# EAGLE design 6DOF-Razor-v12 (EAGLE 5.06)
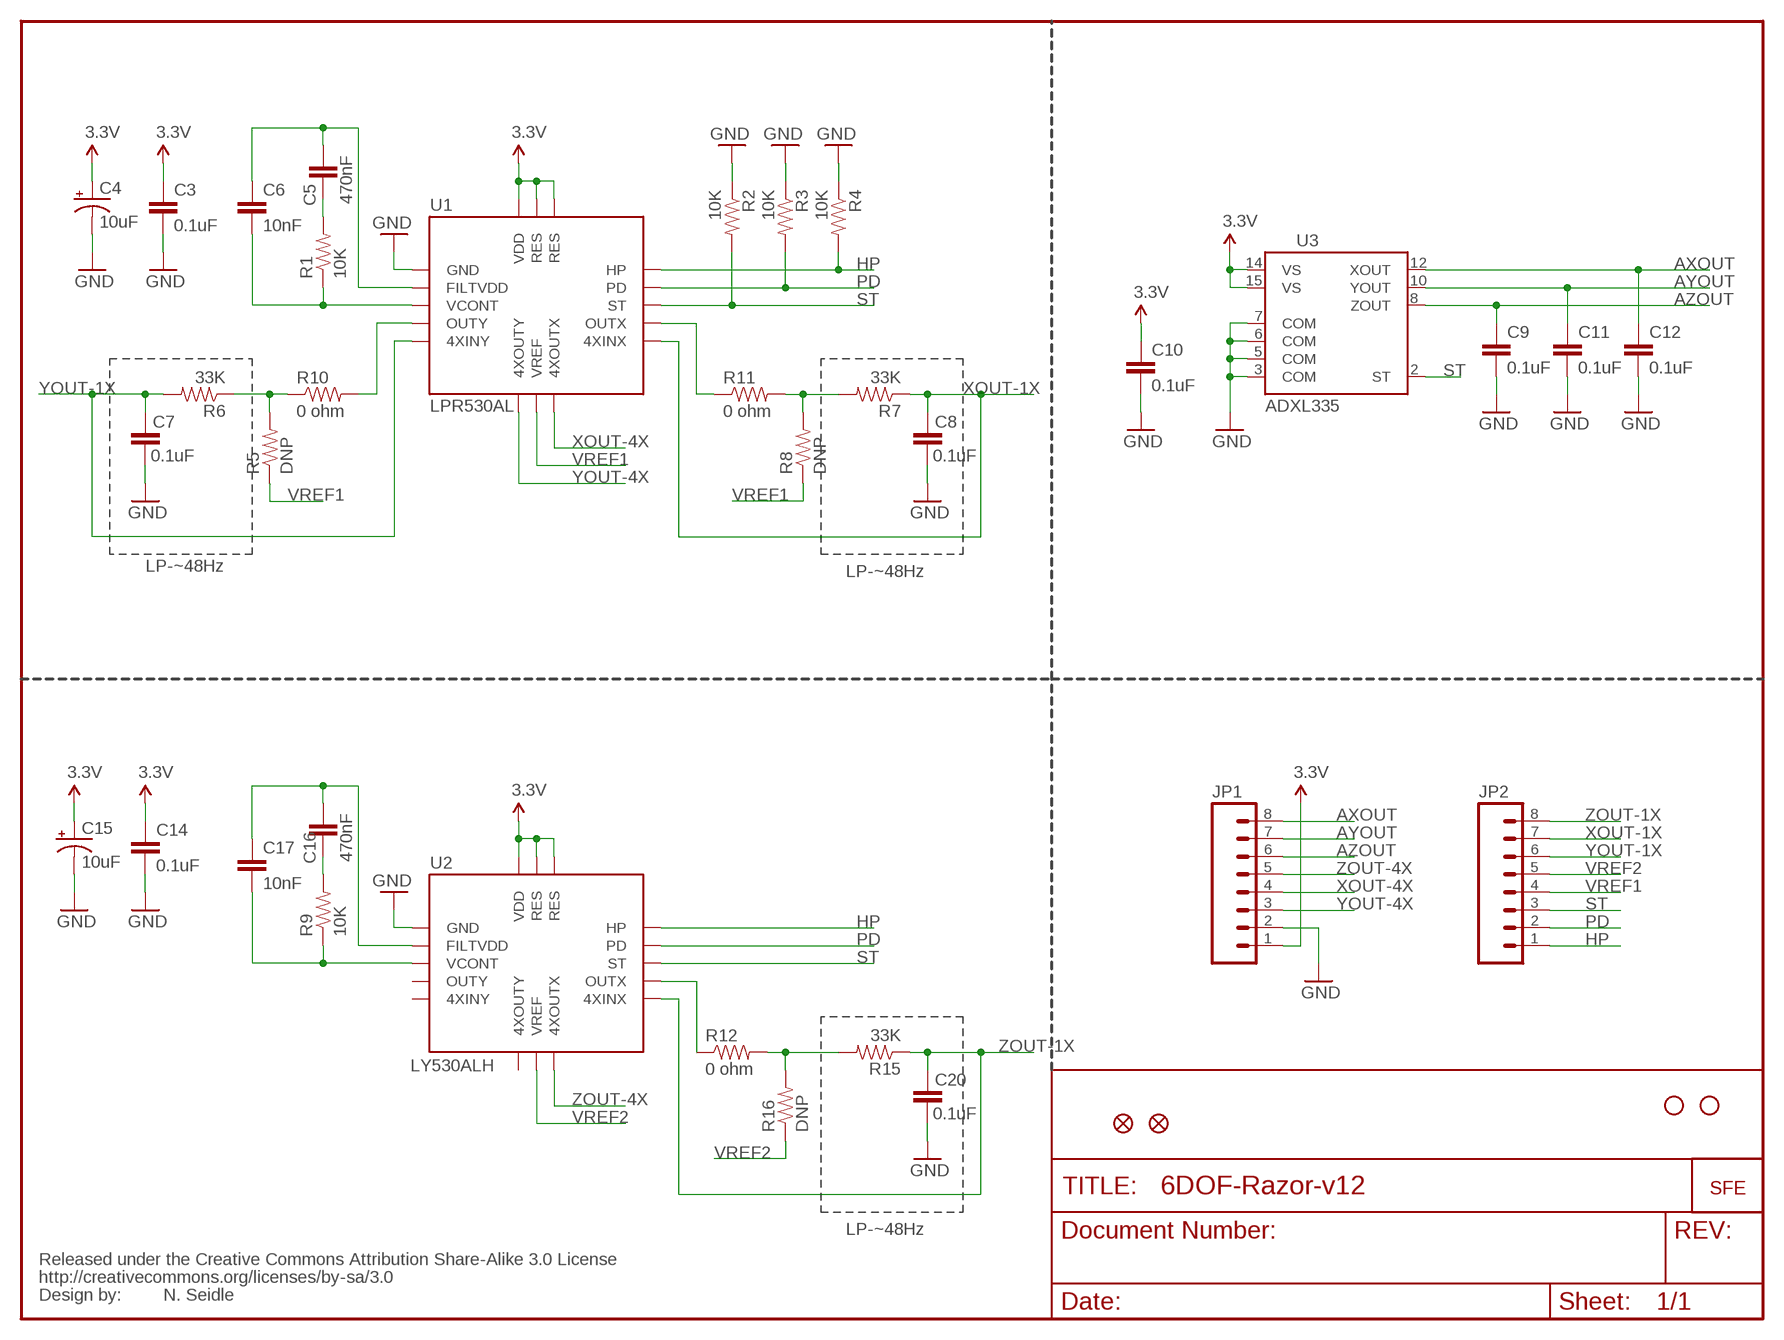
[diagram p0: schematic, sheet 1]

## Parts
C3  0.1uF  CAP0402-CAP  [0402-CAP]
C4  10uF  CAP_POL1206  [EIA3216]
C5  470nF  CAP0402-CAP  [0402-CAP]
C6  10nF  CAP0402-CAP  [0402-CAP]
C7  0.1uF  CAP0402-CAP  [0402-CAP]
C8  0.1uF  CAP0402-CAP  [0402-CAP]
C9  0.1uF  CAP0402-CAP  [0402-CAP]
C10  0.1uF  CAP0402-CAP  [0402-CAP]
C11  0.1uF  CAP0402-CAP  [0402-CAP]
C12  0.1uF  CAP0402-CAP  [0402-CAP]
C14  0.1uF  CAP0402-CAP  [0402-CAP]
C15  10uF  CAP_POL1206  [EIA3216]
C16  470nF  CAP0402-CAP  [0402-CAP]
C17  10nF  CAP0402-CAP  [0402-CAP]
C20  0.1uF  CAP0402-CAP  [0402-CAP]
JP1  M08  [1X08]
JP2  M08  [1X08]
JP3  LOGO-SFENEW  [SFE-NEW-WEBLOGO]
JP4  FIDUCIAL1X2  [FIDUCIAL-1X2]
JP5  FIDUCIAL1X2  [FIDUCIAL-1X2]
R1  10K  RESISTOR0402-RES  [0402-RES]
R2  10K  RESISTOR0402-RES  [0402-RES]
R3  10K  RESISTOR0402-RES  [0402-RES]
R4  10K  RESISTOR0402-RES  [0402-RES]
R5  DNP  RESISTOR0402-RES  [0402-RES]
R6  33K  RESISTOR0402-RES  [0402-RES]
R7  33K  RESISTOR0402-RES  [0402-RES]
R8  DNP  RESISTOR0402-RES  [0402-RES]
R9  10K  RESISTOR0402-RES  [0402-RES]
R10  0 ohm  RESISTOR0402-RES  [0402-RES]
R11  0 ohm  RESISTOR0402-RES  [0402-RES]
R12  0 ohm  RESISTOR0402-RES  [0402-RES]
R15  33K  RESISTOR0402-RES  [0402-RES]
R16  DNP  RESISTOR0402-RES  [0402-RES]
U1  LPR530AL  ST-GYROLGA  [ST-GYRO]
U2  LY530ALH  ST-GYROLGA  [ST-GYRO]
U3  ADXL335  ADXL330SMD  [LFCSP-16]
U$1  CREATIVE_COMMONS  [CREATIVE_COMMONS]
U$2  STAND-OFF  [STAND-OFF]
U$4  STAND-OFF  [STAND-OFF]

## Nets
3.3V: C3.1 C4.A(+) C10.1 C14.1 C15.A(+) JP1.1 U1.14(RES) U1.15(RES) U1.16(VDD) U2.14(RES) U2.15(RES) U2.16(VDD) U3.14(VS) U3.15(VS)
AXOUT: C12.1 JP1.8 U3.12(XOUT)
AYOUT: C11.1 JP1.7 U3.10(YOUT)
AZOUT: C9.1 JP1.6 U3.8(ZOUT)
F1: C5.1 C6.1 U1.2(FILTVDD)
F2: C6.2 R1.1 U1.3(VCONT)
F3: C16.1 C17.1 U2.2(FILTVDD)
F4: C17.2 R9.1 U2.3(VCONT)
GND: C3.2 C4.C(-) C7.1 C8.1 C9.2 C10.2 C11.2 C12.2 C14.2 C15.C(-) C20.1 JP1.2 R2.1 R3.1 R4.1 U1.1(GND) U2.1(GND) U3.3(COM) U3.5(COM) U3.6(COM) U3.7(COM)
HP: JP2.1 R4.2 U1.13(HP) U2.13(HP)
N$1: R10.2 U1.4(OUTY)
N$2: C5.2 R1.2
N$3: R11.1 U1.10(OUTX)
N$4: R5.2 R6.1 R10.1
N$6: R7.2 R8.2 R11.2
N$8: C16.2 R9.2
N$9: R12.1 U2.10(OUTX)
N$10: R12.2 R15.2 R16.2
PD: JP2.2 R3.2 U1.12(PD) U2.12(PD)
ST: JP2.3 R2.2 U1.11(ST) U2.11(ST) U3.2(ST)
VREF1: JP2.4 R5.1 R8.1 U1.7(VREF)
VREF2: JP2.5 R16.1 U2.7(VREF)
XOUT-1X: C8.2 JP2.7 R7.1 U1.9(4XINX)
XOUT-4X: JP1.4 U1.8(4XOUTX)
YOUT-1X: C7.2 JP2.6 R6.2 U1.5(4XINY)
YOUT-4X: JP1.3 U1.6(4XOUTY)
ZOUT-1X: C20.2 JP2.8 R15.1 U2.9(4XINX)
ZOUT-4X: JP1.5 U2.8(4XOUTX)
Unconnected: U2.4(OUTY) U2.5(4XINY) U2.6(4XOUTY)

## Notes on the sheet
- LP-~48Hz
- LP-~48Hz
- LP-~48Hz
- N. Seidle

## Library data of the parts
C3 C5-C12 C14 C16 C17 C20 = SparkFun:CAP: Capacitor
C4 C15 = SparkFun:CAP_POL: Capacitor Polarized
JP1 JP2 = SparkFun:M08: Header 8 Standard 8-pin 0.1" header. Use with straight break away headers (SKU : PRT-00116), right angle break away headers (PRT-00553), swiss pins (PRT-00743), machine pins (PRT-00117), and female headers (PRT-00115).
JP3 = SparkFun:LOGO-SFE: Spark Fun Electronics PCB Logo
JP4 JP5 = SparkFun:FIDUCIAL: Fiducial Alignment Points
R1-R12 R15 R16 = SparkFun:RESISTOR: Resistor
U1 U2 = SparkFun:ST-GYRO
U3 = SparkFun:ADXL330: Triple Axis Accelerometer Analog Devices ADXL330 +/-3g 2.4V-5.25V Analog output. Spark Fun Electronics SKU : COM-00730. Center pad paste layer has been reduced to avoid shorting.
U$1 = SparkFun:CREATIVE_COMMONS
U$2 U$4 = SparkFun:STAND-OFF: Stand Off

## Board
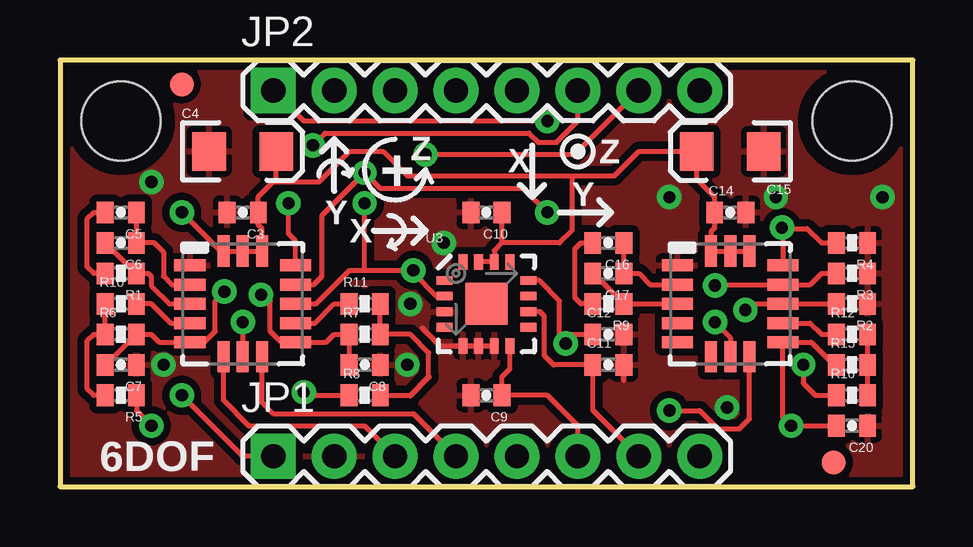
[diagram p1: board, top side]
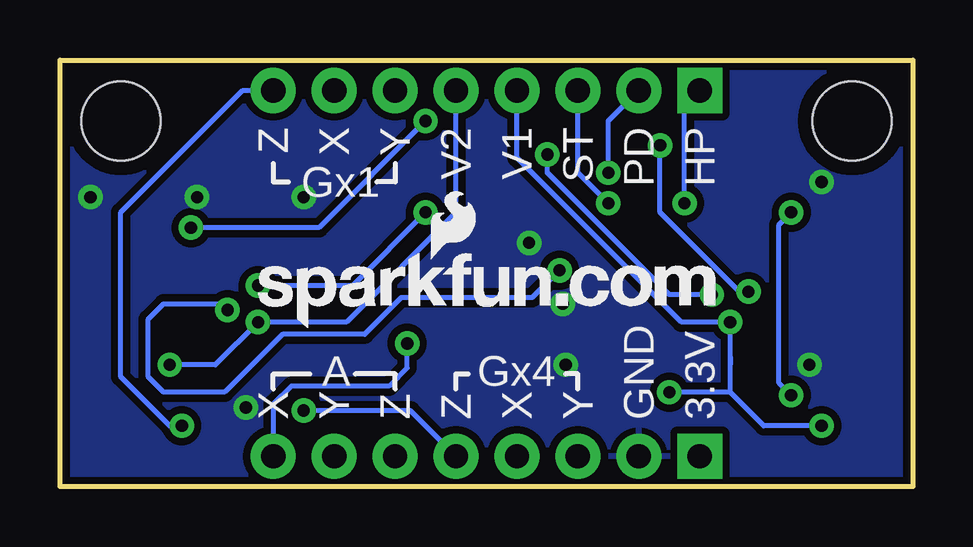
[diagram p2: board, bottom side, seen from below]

Size 35.56 x 17.78 mm. Coordinates in mm from the lower left corner, seen from the top.
Outline: 0,0 35.56,0 35.56,17.78 0,17.78 0,0
Copper layers (1*16): Top 0.035mm / dielectric 1.5mm / Bottom 0.035mm
Design rules "SparkFun": minimum track width 8mil, minimum drill 20mil, track to track 8mil, track to pad 8mil, pad to pad 8mil, via to via 8mil, smd to smd 8mil, copper to edge 9mil, drill to drill 8mil, minimum pad ring 12mil, minimum via ring 10mil, stop-mask expansion 4mil, vias tented up to drill 20mil, thermal gap 10mil

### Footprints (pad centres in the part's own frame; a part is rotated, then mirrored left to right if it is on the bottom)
0402-CAP = smd 0.7 x 0.9: 1 -0.65,0; 2 0.65,0
EIA3216 = smd 1.4 x 1.6: A 1.4,0; C -1.4,0
1X08 = drill 1.016 pad 1.88 square: 1 0,0 | drill 1.016 pad 1.88 round: 2 2.54,0; 3 5.08,0; 4 7.62,0; 5 10.16,0; 6 12.7,0; 7 15.24,0; 8 17.78,0
FIDUCIAL-1X2 = smd 1 x 1: 1 0,0
0402-RES = smd 0.7 x 0.9: 1 -0.65,0; 2 0.65,0
ST-GYRO@1 = smd 1.3 x 0.5: 1 -2.2,1.6; 2 -2.2,0.8; 3 -2.2,0; 4 -2.2,-0.8; 5 -2.2,-1.6; 9 2.2,-1.6; 10 2.2,-0.8; 11 2.2,0; 12 2.2,0.8; 13 2.2,1.6 | smd 0.5 x 1.3: 6 -0.8,-2.2; 7 0,-2.2; 8 0.8,-2.2; 14 0.8,2.2; 15 0,2.2; 16 -0.8,2.2
LFCSP-16 = smd 1.75 x 1.75: 0 0,0 | smd 0.65 x 0.37: 1 -1.75,0.975; 2 -1.75,0.325; 3 -1.75,-0.325; 4 -1.75,-0.975; 9 1.75,-0.975; 10 1.75,-0.325; 11 1.75,0.325; 12 1.75,0.975 | smd 0.37 x 0.65: 5 -0.975,-1.75; 6 -0.325,-1.75; 7 0.325,-1.75; 8 0.975,-1.75; 13 0.975,1.75; 14 0.325,1.75; 15 -0.325,1.75; 16 -0.975,1.75
STAND-OFF = hole 3.302: 0,0

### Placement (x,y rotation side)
C3  7.62,11.43 180 top
C4  7.62,13.97 0 top
C5  2.54,11.43 180 top
C6  2.54,10.16 180 top
C7  2.54,5.08 180 top
C8  12.7,5.08 180 top
C9  17.78,3.81 180 top
C10  17.78,11.43 180 top
C11  22.86,5.08 0 top
C12  22.86,6.35 0 top
C14  27.94,11.43 0 top
C15  27.94,13.97 180 top
C16  22.86,10.16 180 top
C17  22.86,8.89 180 top
C20  33.02,2.54 180 top
JP1  8.89,1.27 0 top
JP2  8.89,16.51 0 top
JP3  27.3,6.6 0 bottom
JP4  32.26,1.02 0 top
JP5  5.08,16.76 0 top
R1  2.54,8.89 180 top
R2  33.02,7.62 180 top
R3  33.02,8.89 180 top
R4  33.02,10.16 180 top
R5  2.54,3.81 180 top
R6  2.54,6.35 0 top
R7  12.7,6.35 0 top
R8  12.7,3.81 0 top
R9  22.86,7.62 180 top
R10  2.54,7.62 0 top
R11  12.7,7.62 0 top
R12  33.02,6.35 0 top
R15  33.02,5.08 0 top
R16  33.02,3.81 0 top
U1  LPR530AL  [ST-GYRO@1]  7.62,7.62 0 top
U2  LY530ALH  [ST-GYRO@1]  27.94,7.62 0 top
U3  17.78,7.62 0 top
U$1  not placed on the board
U$2  2.54,15.24 0 top
U$4  33.02,15.24 0 top

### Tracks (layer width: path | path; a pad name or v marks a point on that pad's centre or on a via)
3.3V  (via drill 0.51)
  Top 0.203: U1.14 8.42,10.76 8.27,10.91 C3.1 8.27,12.08 8.89,12.7 9.02,12.7 | U1.14 U1.15 U1.16 6.69,9.82 v5.08,11.43 | U3.15 U3.14 18.11,9.85 18.41,10.16 | U2.14 U2.15 U2.16 | U1.14 8.55,9.82 | JP1.1 7.62,1.27 v5.08,3.81 | U2.16 27.01,9.82 | U2.16 27.14,10.63 27.29,10.78 C14.1 27.29,12.08 26.54,12.83 C15.A 24.13,13.97 23.11,12.95 21.34,12.95 | C10.1 18.43,10.18 18.41,10.16 | C4.A 9.02,12.7 | 18.41,10.16 20.83,10.16 21.34,10.67 21.34,12.95 | 21.34,12.95 14.48,12.95 13.46,13.97 12.06,13.97 10.79,12.7 9.02,12.7
  Bottom 0.203: v5.08,3.81 5.59,4.32 5.59,10.92 v5.08,11.43
AXOUT  (via drill 0.51)
  Top 0.203: U3.12 19.98,8.6 20.83,7.75 20.83,6.22 v21.08,5.97 21.08,6.35 C12.1
  Bottom 0.203: JP1.8 26.67,3.43 25.91,4.19 21.84,4.19 21.08,4.95 v21.08,5.97
AYOUT
  Top 0.203: JP1.7 22.21,3.19 C11.1 20.57,5.08 20.19,5.46 20.19,7.11 20.01,7.29 U3.10
AZOUT
  Top 0.203: JP1.6 21.59,2.54 20.32,3.81 C9.1 18.43,4.59 18.75,4.91 U3.8
F1
  Top 0.203: C5.1 C6.1 3.94,10.16 4.32,9.78 4.32,8.76 4.66,8.42 U1.2
F2
  Top 0.203: C6.2 3.16,8.89 R1.1 3.68,8.89 3.81,8.76 3.81,8.38 4.57,7.62 U1.3
F3
  Top 0.203: C16.1 C17.1 24.13,8.89 24.6,8.42 U2.2
F4
  Top 0.203: U2.3 R9.1 22.24,8.89 C17.2
GND  (via drill 0.51)
  Top 0.203: U3.7 U3.6 U3.5 15.85,5.87 15.11,6.6 | 23.51,4.43 C11.2
  other vias: 3.81,12.7 27.81,3.3 25.4,12.06 34.29,12.06 4.32,5.08 29.84,12.06 16,10.16 14.48,5.08 14.61,7.62
  pour Bottom (isolate 0.305): 0,17.78 35.56,17.78 35.56,0 0,0
  pour Top (isolate 0.305): 0,17.78 35.56,17.78 35.56,0 0,0
HP  (via drill 0.51)
  Top 0.203: JP2.1 10.16,15.24 v20.32,15.24 | 30.14,10.75 U2.13 | v30.1,10.79 30.14,10.75 | U1.13 9.82,10.25 9.53,10.54 v9.53,11.81 | 30.14,10.75 31.16,10.75 31.75,10.16 R4.2
  Bottom 0.203: v30.1,10.79 24.77,10.79 v20.32,15.24 | v9.53,11.81 9.53,15.88 JP2.1
N$1
  Top 0.203: U1.4 4.61,6.82 3.81,7.62 R10.2
N$2
  Top 0.203: 1.52,8.89 R1.2 1.4,8.89 1.14,9.14 1.14,11.18 1.4,11.43 C5.2
N$3
  Top 0.203: U1.10 10.63,6.82 11.43,7.62 R11.1
N$4
  Top 0.203: R5.2 1.4,3.81 1.14,4.06 1.14,6.1 1.4,6.35 R6.1 R10.1
N$6
  Top 0.203: R8.2 14.61,3.81 | 15.37,4.57 15.37,5.59 14.61,6.35 R7.2 R11.2
  Top 0.254: 14.61,3.81 15.37,4.57
N$8
  Top 0.203: C16.2 21.72,10.16 21.46,9.91 21.46,7.87 21.72,7.62 R9.2
N$9
  Top 0.203: U2.10 31.28,6.82 31.75,6.35 R12.1
N$10
  Top 0.203: R16.2 R15.2 R12.2
PD  (via drill 0.51)
  Top 0.203: U1.12 10.58,8.42 10.92,8.76 10.92,11.3 v12.7,13.08 13.34,12.45 19.3,12.45 v20.32,11.43 | R3.2 31.75,8.89 31.28,8.42 U2.12 27.39,8.42 v27.3,8.38
  Bottom 0.203: v12.7,13.08 12.7,15.24 JP2.2 | v27.3,8.38 23.37,8.38 v20.32,11.43
ST  (via drill 0.51)
  Top 0.203: U1.11 10.67,7.62 12.06,9.02 12.7,9.02 | R2.2 U2.11 28.83,7.62 v28.57,7.37 | 12.7,9.02 v12.7,11.81 | 12.7,9.02 v14.73,9.02 14.73,8.89 15.68,7.95 U3.2
  Bottom 0.203: v28.57,7.37 28.83,7.62 31.24,7.62 31.88,6.99 31.88,4.57 31.24,3.94 28.7,3.94 26.29,6.35 22.86,6.35 21.34,7.87 15.88,7.87 v14.73,9.02 | JP2.3 13.97,13.08 v12.7,11.81
VREF1  (via drill 0.51)
  Top 0.203: R5.1 3.19,3.16 v3.81,2.54 | v7.62,6.86 U1.7 | R8.1 10.29,3.81 v10.16,3.94
  Bottom 0.203: JP2.4 16.51,13.72 9.65,6.86 v7.62,6.86 U1.7 | U1.7 7.62,5.08 | 7.62,3.94 v10.16,3.94 | 7.62,3.94 U1.7 | v3.81,2.54 6.22,2.54 7.62,3.94
VREF2  (via drill 0.51)
  Top 0.203: R16.1 31.5,3.81 30.99,4.32 v30.99,5.08 | U2.7 27.94,6.22 v27.3,6.86
  Bottom 0.203: JP2.5 19.05,11.43 23.62,6.86 v27.3,6.86 29.08,5.08 v30.99,5.08
XOUT-1X  (via drill 0.51)
  Top 0.203: JP2.7 21.46,13.84 v15.24,13.84 | C8.2 R7.1 11.43,6.35 11.1,6.02 U1.9 9.22,6.02 8.76,6.48 8.76,7.75 v8.38,8
  Bottom 0.203: v15.24,13.84 15.24,13.08 10.16,8 v8.38,8
XOUT-4X
  Top 0.203: U1.8 8.42,3.52 8.89,3.05 14.73,3.05 JP1.4
YOUT-1X  (via drill 0.51)
  Top 0.203: C7.2 R6.2 3.81,6.35 4.14,6.02 U1.5 6.02,6.02 6.48,6.48 6.48,7.75 v6.86,8.13 | JP2.6 21.59,15.24 20.7,14.35 19.94,14.35 19.56,14.73 11.05,14.73 v10.54,14.22
  Bottom 0.203: v6.86,8.13 7.24,8.13 10.54,11.43 v10.54,14.22
YOUT-4X
  Top 0.203: U1.6 6.82,3.59 7.87,2.54 12.7,2.54 JP1.3
ZOUT-1X  (via drill 0.51)
  Top 0.203: C20.2 v30.48,2.54 30.14,2.88 U2.9 31.32,6.02 32.26,5.08 R15.1
  Bottom 0.203: JP2.8 27.94,16.51 33.02,11.43 33.02,4.57 30.99,2.54 v30.48,2.54
ZOUT-4X  (via drill 0.51)
  Top 0.203: U2.8 28.74,2.83 28.32,2.41 27.43,2.41 26.67,3.17 v25.4,3.17
  Bottom 0.203: v25.4,3.17 20.95,3.17 JP1.5

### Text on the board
tPlace: Z | X | Z | + | Y | Y | X | 6DOF | N. Seidle
bPlace: HP | PD | ST | V1 | V2 | Y | X | Z | Gx1 | Gx4 | A | 3.3V | GND | Y | X | Z | Z | Y | X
